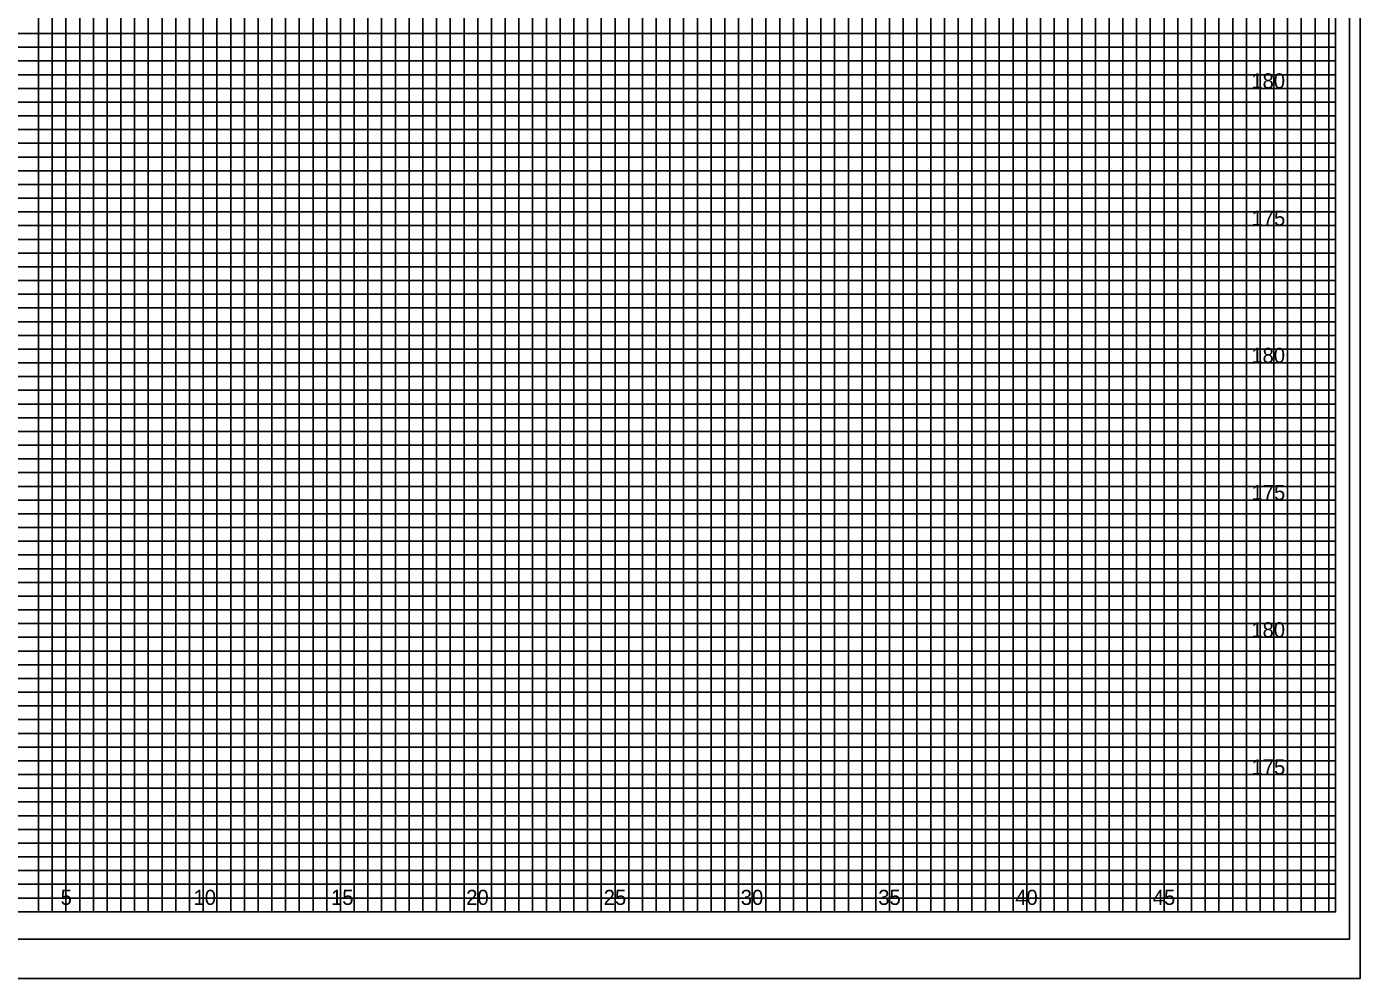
# Model space of a CAD drawing. Extents: x -4 to 103, y -2 to 280.
# Drawn here: x 54.82 to 103.4, y 139.22 to 173.9 of the extents above; entities that cross this region are included whole.
import ezdxf

# ---------------------------------------------------------------- set-up
doc = ezdxf.new("R2010")
doc.units = 0
for name, color, linetype in [('Exist XS Center Line Elevation Label', 7, 'Continuous'), ('Old_Level_63', 7, 'Continuous'), ('Prop XS Dump Level', 7, 'Continuous'), ('Prop XS Pvmt Edge Slope', 7, 'Continuous'), ('Prop XS SE Text', 7, 'Continuous'), ('Prop XS Subgrade Earthwork', 7, 'Continuous'), ('Sheet Cutting Line CELL', 7, 'Continuous'), ('Sheet Plot Border Inside CELL', 7, 'Continuous'), ('Sheet Plot Border Outside CELL', 7, 'Continuous')]:
    doc.layers.add(name, color=color, linetype=linetype)

msp = doc.modelspace()

# ---------------------------------------------------------------- linework, layer by layer
at = {"layer": 'Exist XS Center Line Elevation Label'}
for points in [[(56.25, 141.65), (56.25, 206.65)], [(58.75, 206.65), (58.75, 141.65), (61.25, 141.65), (61.25, 206.65)], [(63.75, 206.65), (63.75, 141.65), (66.25, 141.65), (66.25, 206.65)], [(68.75, 206.65), (68.75, 141.65), (71.25, 141.65), (71.25, 206.65)], [(73.75, 206.65), (73.75, 141.65), (76.25, 141.65), (76.25, 203.65)], [(88.75, 203.65), (88.75, 141.65), (91.25, 141.65), (91.25, 205.075)], [(93.75, 205.075), (93.75, 141.65), (96.25, 141.65), (96.25, 205.075)], [(98.75, 205.075), (98.75, 141.65), (101.25, 141.65), (101.25, 205.075)], [(78.75, 203.65), (78.75, 141.65), (81.25, 141.65), (81.25, 203.65)], [(83.75, 203.65), (83.75, 141.65), (86.25, 141.65), (86.25, 203.65)], [(0, 169.15), (102.5, 169.15), (102.5, 171.65), (0, 171.65)], [(0, 164.15), (102.5, 164.15), (102.5, 166.65), (0, 166.65)], [(0, 159.15), (102.5, 159.15), (102.5, 161.65), (0, 161.65)], [(0, 154.15), (102.5, 154.15), (102.5, 156.65), (0, 156.65)], [(0, 149.15), (102.5, 149.15), (102.5, 151.65), (0, 151.65)], [(0, 144.15), (102.5, 144.15), (102.5, 146.65), (0, 146.65)]]:
    msp.add_lwpolyline(points, dxfattribs=at)
at = {"layer": 'Old_Level_63'}
msp.add_lwpolyline([(102.5, 206.65), (0, 206.65), (0, 141.65), (102.5, 141.65)], close=True, dxfattribs=at)
at = {"layer": 'Prop XS Dump Level'}
for p, q in [((56.25, 141.65), (56.25, 206.65)), ((58.75, 141.65), (58.75, 206.65)), ((61.25, 141.65), (61.25, 206.65)), ((63.75, 141.65), (63.75, 206.65)), ((66.25, 141.65), (66.25, 206.65)), ((68.75, 141.65), (68.75, 206.65)), ((71.25, 141.65), (71.25, 206.65)), ((73.75, 141.65), (73.75, 206.65)), ((91.25, 141.65), (91.25, 205.075)), ((93.75, 141.65), (93.75, 205.075)), ((96.25, 141.65), (96.25, 205.075)), ((98.75, 141.65), (98.75, 205.075)), ((101.25, 141.65), (101.25, 205.075)), ((76.25, 141.65), (76.25, 203.65)), ((78.75, 141.65), (78.75, 203.65)), ((81.25, 141.65), (81.25, 203.65)), ((83.75, 141.65), (83.75, 203.65)), ((86.25, 141.65), (86.25, 203.65)), ((88.75, 141.65), (88.75, 203.65)), ((0, 171.65), (102.5, 171.65)), ((0, 169.15), (102.5, 169.15)), ((0, 166.65), (102.5, 166.65)), ((0, 164.15), (102.5, 164.15)), ((0, 161.65), (102.5, 161.65)), ((0, 159.15), (102.5, 159.15)), ((0, 156.65), (102.5, 156.65)), ((0, 154.15), (102.5, 154.15)), ((0, 151.65), (102.5, 151.65)), ((0, 149.15), (102.5, 149.15)), ((0, 146.65), (102.5, 146.65)), ((0, 144.15), (102.5, 144.15))]:
    msp.add_line(p, q, dxfattribs=at)
at = {"layer": 'Prop XS SE Text'}
for points in [[(54.75, 141.65), (55.25, 141.65), (55.25, 206.65)], [(55.75, 206.65), (55.75, 141.65), (56.75, 141.65), (56.75, 206.65)], [(57.25, 206.65), (57.25, 141.65), (57.75, 141.65), (57.75, 206.65)], [(58.25, 206.65), (58.25, 141.65), (59.25, 141.65), (59.25, 206.65)], [(59.75, 206.65), (59.75, 141.65), (60.25, 141.65), (60.25, 206.65)], [(60.75, 206.65), (60.75, 141.65), (61.75, 141.65), (61.75, 206.65)], [(62.25, 206.65), (62.25, 141.65), (62.75, 141.65), (62.75, 206.65)], [(63.25, 206.65), (63.25, 141.65), (64.25, 141.65), (64.25, 206.65)], [(64.75, 206.65), (64.75, 141.65), (65.25, 141.65), (65.25, 206.65)], [(65.75, 206.65), (65.75, 141.65), (66.75, 141.65), (66.75, 206.65)], [(67.25, 206.65), (67.25, 141.65), (67.75, 141.65), (67.75, 206.65)], [(68.25, 206.65), (68.25, 141.65), (69.25, 141.65), (69.25, 206.65)], [(69.75, 206.65), (69.75, 141.65), (70.25, 141.65), (70.25, 206.65)], [(70.75, 206.65), (70.75, 141.65), (71.75, 141.65), (71.75, 206.65)], [(72.25, 206.65), (72.25, 141.65), (72.75, 141.65), (72.75, 206.65)], [(73.25, 206.65), (73.25, 141.65), (74.25, 141.65), (74.25, 203.65)], [(89.75, 203.65), (89.75, 141.65), (90.25, 141.65), (90.25, 205.075)], [(90.75, 205.075), (90.75, 141.65), (91.75, 141.65), (91.75, 205.075)], [(92.25, 205.075), (92.25, 141.65), (92.75, 141.65), (92.75, 205.075)], [(93.25, 205.075), (93.25, 141.65), (94.25, 141.65), (94.25, 205.075)], [(94.75, 205.075), (94.75, 141.65), (95.25, 141.65), (95.25, 205.075)], [(95.75, 205.075), (95.75, 141.65), (96.75, 141.65), (96.75, 205.075)], [(97.25, 205.075), (97.25, 141.65), (97.75, 141.65), (97.75, 205.075)], [(98.25, 205.075), (98.25, 141.65), (99.25, 141.65), (99.25, 205.075)], [(99.75, 205.075), (99.75, 141.65), (100.25, 141.65), (100.25, 205.075)], [(100.25, 205.075), (100.75, 205.075), (100.75, 141.65), (101.75, 141.65), (101.75, 205.075), (102.25, 205.075), (102.25, 141.65)], [(74.75, 203.65), (74.75, 141.65), (75.25, 141.65), (75.25, 203.65)], [(75.75, 203.65), (75.75, 141.65), (76.75, 141.65), (76.75, 203.65)], [(77.25, 203.65), (77.25, 141.65), (77.75, 141.65), (77.75, 203.65)], [(78.25, 203.65), (78.25, 141.65), (79.25, 141.65), (79.25, 203.65)], [(79.75, 203.65), (79.75, 141.65), (80.25, 141.65), (80.25, 203.65)], [(80.75, 203.65), (80.75, 141.65), (81.75, 141.65), (81.75, 203.65)], [(82.25, 203.65), (82.25, 141.65), (82.75, 141.65), (82.75, 203.65)], [(83.25, 203.65), (83.25, 141.65), (84.25, 141.65), (84.25, 203.65)], [(84.75, 203.65), (84.75, 141.65), (85.25, 141.65), (85.25, 203.65)], [(85.75, 203.65), (85.75, 141.65), (86.75, 141.65), (86.75, 203.65)], [(87.25, 203.65), (87.25, 141.65), (87.75, 141.65), (87.75, 203.65)], [(88.25, 203.65), (88.25, 141.65), (89.25, 141.65), (89.25, 203.65)], [(0, 173.15), (102.5, 173.15), (102.5, 173.65), (0, 173.65)], [(0, 172.15), (102.5, 172.15), (102.5, 172.65), (0, 172.65)], [(0, 170.65), (102.5, 170.65), (102.5, 171.15), (0, 171.15)], [(0, 169.65), (102.5, 169.65), (102.5, 170.15), (0, 170.15)], [(0, 168.15), (102.5, 168.15), (102.5, 168.65), (0, 168.65)], [(0, 167.15), (102.5, 167.15), (102.5, 167.65), (0, 167.65)], [(0, 165.65), (102.5, 165.65), (102.5, 166.15), (0, 166.15)], [(0, 164.65), (102.5, 164.65), (102.5, 165.15), (0, 165.15)], [(0, 163.15), (102.5, 163.15), (102.5, 163.65), (0, 163.65)], [(0, 162.15), (102.5, 162.15), (102.5, 162.65), (0, 162.65)], [(0, 160.65), (102.5, 160.65), (102.5, 161.15), (0, 161.15)], [(0, 159.65), (102.5, 159.65), (102.5, 160.15), (0, 160.15)], [(0, 158.15), (102.5, 158.15), (102.5, 158.65), (0, 158.65)], [(0, 157.15), (102.5, 157.15), (102.5, 157.65), (0, 157.65)], [(0, 155.65), (102.5, 155.65), (102.5, 156.15), (0, 156.15)], [(0, 154.65), (102.5, 154.65), (102.5, 155.15), (0, 155.15)], [(0, 153.15), (102.5, 153.15), (102.5, 153.65), (0, 153.65)], [(0, 152.15), (102.5, 152.15), (102.5, 152.65), (0, 152.65)], [(0, 150.65), (102.5, 150.65), (102.5, 151.15), (0, 151.15)], [(0, 149.65), (102.5, 149.65), (102.5, 150.15), (0, 150.15)], [(0, 148.15), (102.5, 148.15), (102.5, 148.65), (0, 148.65)], [(0, 147.15), (102.5, 147.15), (102.5, 147.65), (0, 147.65)], [(0, 145.65), (102.5, 145.65), (102.5, 146.15), (0, 146.15)], [(0, 144.65), (102.5, 144.65), (102.5, 145.15), (0, 145.15)], [(0, 143.15), (102.5, 143.15), (102.5, 143.65), (0, 143.65)], [(0, 142.15), (102.5, 142.15), (102.5, 142.65), (0, 142.65)]]:
    msp.add_lwpolyline(points, dxfattribs=at)
at = {"layer": 'Sheet Cutting Line CELL'}
msp.add_line((-3.5, 139.225), (103.4, 139.225), dxfattribs=at)
at = {"layer": 'Sheet Plot Border Inside CELL'}
msp.add_lwpolyline([(103, 207.65), (-2.8, 207.65), (-2.8, 140.65), (103, 140.65)], close=True, dxfattribs=at)
at = {"layer": 'Sheet Plot Border Outside CELL'}
msp.add_lwpolyline([(103.4, 209.05), (-3.5, 209.05), (-3.5, 139.225), (103.4, 139.225)], close=True, dxfattribs=at)

# ---------------------------------------------------------------- texts
at = {"layer": 'Prop XS Pvmt Edge Slope'}
for s, p in [('5', (56.057, 141.9)), ('10', (60.897, 141.9)), ('15', (65.906, 141.9)), ('20', (70.831, 141.9)), ('25', (75.84, 141.9)), ('30', (80.831, 141.9)), ('35', (85.84, 141.9)), ('40', (90.831, 141.9)), ('45', (95.84, 141.9))]:
    msp.add_text(s, height=0.55, dxfattribs=at).set_placement(p)
at = {"layer": 'Prop XS Subgrade Earthwork'}
for s, p in [('180', (99.43, 171.65)), ('175', (99.438, 166.65)), ('180', (99.43, 161.65)), ('175', (99.438, 156.65)), ('180', (99.43, 151.65)), ('175', (99.438, 146.65))]:
    msp.add_text(s, height=0.55, dxfattribs=at).set_placement(p)

doc.saveas('drawing.dxf')
